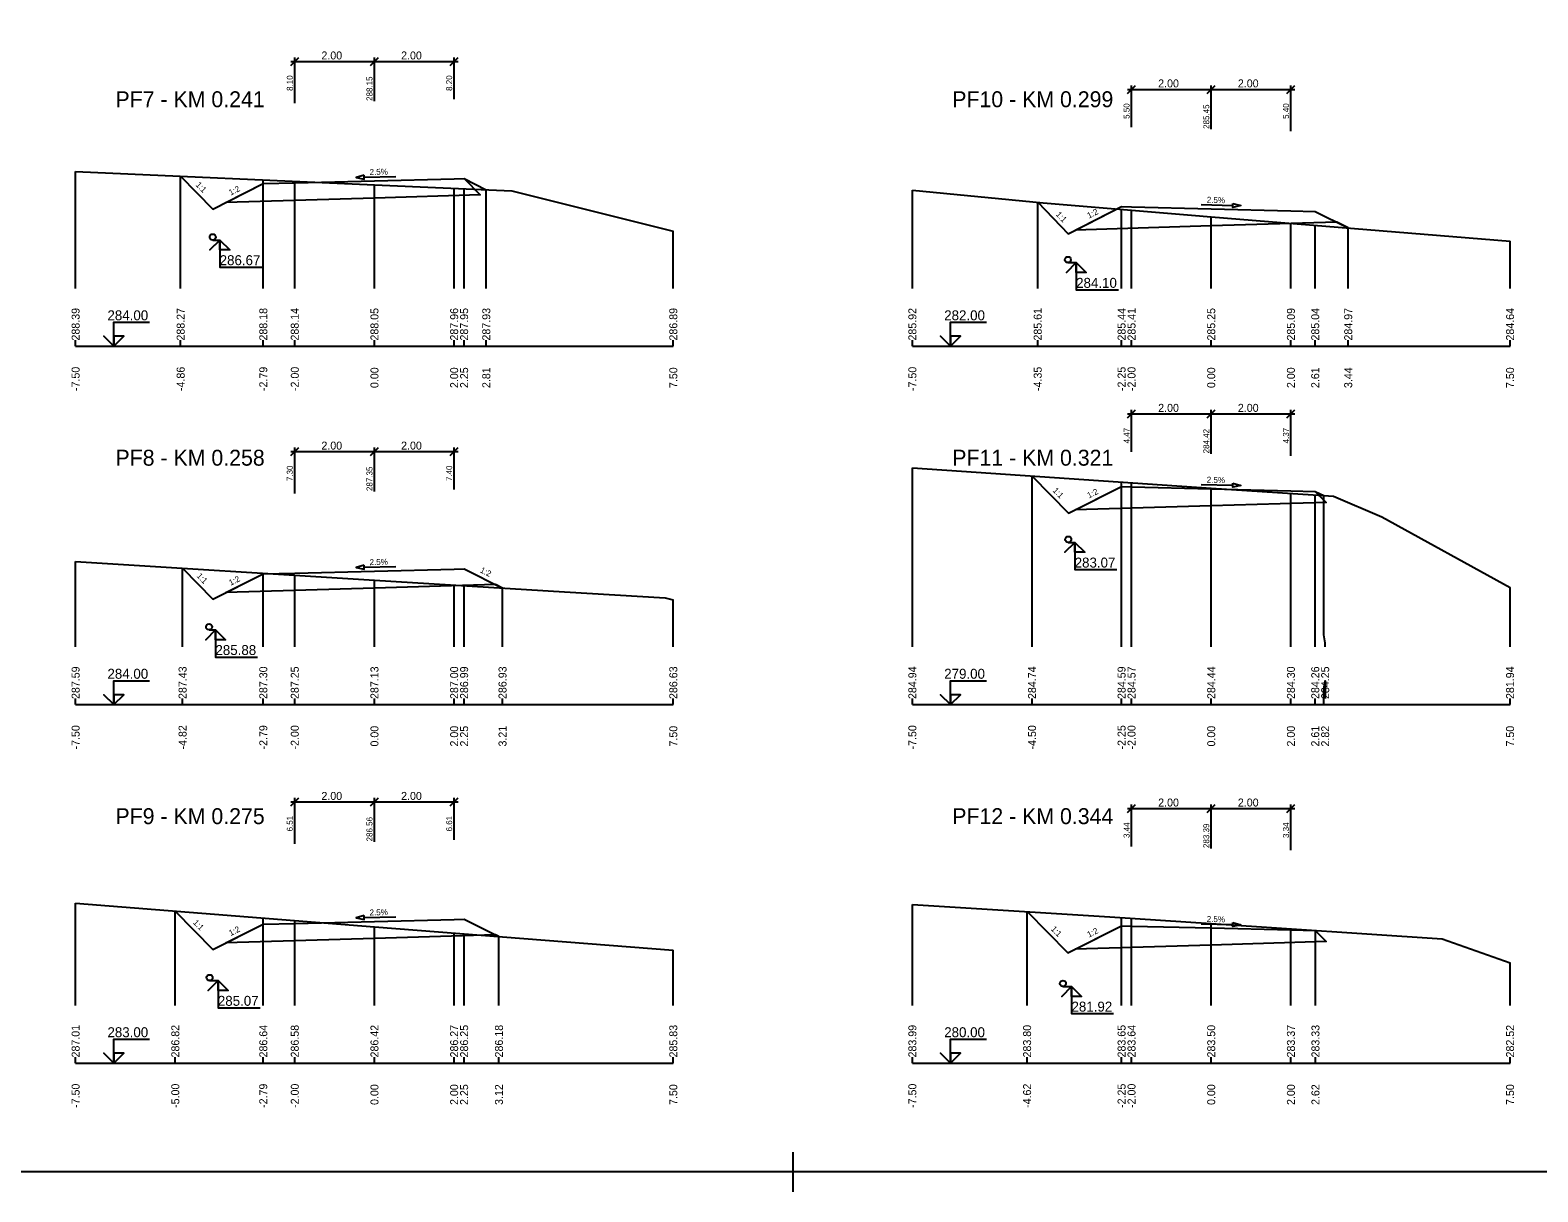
# Model space of a CAD drawing. Extents: x -5 to 1895, y -2 to 602.
# Drawn here: x 438.6 to 817, y -2.3 to 289.4 of the extents above; entities that cross this region are included whole.
import ezdxf

# ---------------------------------------------------------------- set-up
doc = ezdxf.new("R2010")
doc.units = 0
for name, color, linetype in [('KOTA', 7, 'Continuous'), ('KOTA_DELKY', 7, 'Continuous'), ('KOTA_DELKY_CONT', 7, 'Continuous'), ('KRIZENI', 7, 'Continuous'), ('NS_TELESO_VOZOVKY', 7, 'Continuous'), ('NS_V_PF', 7, 'Continuous'), ('REZY_PF_PUVODNI', 7, 'Continuous'), ('SESTAVY_REZU_PF', 7, 'Continuous'), ('SKLON', 7, 'Continuous'), ('SVK', 7, 'Continuous')]:
    doc.layers.add(name, color=color, linetype=linetype)

msp = doc.modelspace()

# ---------------------------------------------------------------- linework, layer by layer
for p, q in [((630, 7.67), (630, -2.33)), ((630, 7.67), (630, -2.33)), ((630, 7.67), (630, -2.33)), ((630, 7.67), (630, -2.33)), ((630, 7.67), (630, -2.33)), ((630, 7.67), (630, -2.33)), ((630, 7.67), (630, -2.33)), ((630, 7.67), (630, -2.33)), ((630, 7.67), (630, -2.33)), ((630, 7.67), (630, -2.33)), ((630, 7.67), (630, -2.33)), ((630, 7.67), (630, -2.33)), ((635, 2.67), (625, 2.67)), ((635, 2.67), (625, 2.67)), ((635, 2.67), (625, 2.67)), ((635, 2.67), (625, 2.67)), ((635, 2.67), (625, 2.67)), ((635, 2.67), (625, 2.67)), ((635, 2.67), (625, 2.67)), ((635, 2.67), (625, 2.67)), ((635, 2.67), (625, 2.67)), ((635, 2.67), (625, 2.67)), ((635, 2.67), (625, 2.67)), ((635, 2.67), (625, 2.67))]:
    msp.add_line(p, q)
msp.add_lwpolyline([(0, 596.67), (1890, 596.67), (1890, 2.67), (0, 2.67)], close=True)
at = {"layer": 'KOTA'}
for points in [[(486.2, 236.66), (483.7, 234.16), (486.2, 236.66), (486.2, 229.84), (496.74, 229.84)], [(484.41, 236.66), (486.2, 236.66)], [(486.2, 236.66), (488.7, 234.16), (486.2, 234.16), (486.2, 236.66)], [(486.2, 236.66), (488.7, 234.16), (486.2, 234.16)], [(701.14, 230.97), (698.64, 228.47), (701.14, 230.97), (701.14, 224.15), (711.69, 224.15)], [(699.03, 230.97), (701.14, 230.97)], [(701.14, 230.97), (703.64, 228.47), (701.14, 228.47), (701.14, 230.97)], [(701.14, 230.97), (703.64, 228.47), (701.14, 228.47)], [(459.57, 210), (457.07, 212.5), (459.57, 210), (459.57, 216), (468.57, 216)], [(669.57, 210), (667.07, 212.5), (669.57, 210), (669.57, 216), (678.57, 216)], [(459.57, 210), (462.07, 212.5), (459.57, 212.5), (459.57, 210)], [(459.57, 210), (462.07, 212.5), (459.57, 212.5)], [(669.57, 210), (672.07, 212.5), (669.57, 212.5), (669.57, 210)], [(669.57, 210), (672.07, 212.5), (669.57, 212.5)], [(700.78, 160.74), (698.28, 158.24), (700.78, 160.74), (700.78, 153.92), (711.32, 153.92)], [(699.13, 160.74), (700.78, 160.74)], [(700.78, 160.74), (703.28, 158.24), (700.78, 158.24), (700.78, 160.74)], [(700.78, 160.74), (703.28, 158.24), (700.78, 158.24)], [(485.14, 138.78), (482.64, 136.28), (485.14, 138.78), (485.14, 131.96), (495.68, 131.96)], [(483.49, 138.78), (485.14, 138.78)], [(485.14, 138.78), (487.64, 136.28), (485.14, 136.28), (485.14, 138.78)], [(485.14, 138.78), (487.64, 136.28), (485.14, 136.28)], [(459.57, 120), (457.07, 122.5), (459.57, 120), (459.57, 126), (468.57, 126)], [(669.57, 120), (667.07, 122.5), (669.57, 120), (669.57, 126), (678.57, 126)], [(459.57, 120), (462.07, 122.5), (459.57, 122.5), (459.57, 120)], [(459.57, 120), (462.07, 122.5), (459.57, 122.5)], [(669.57, 120), (672.07, 122.5), (669.57, 122.5), (669.57, 120)], [(669.57, 120), (672.07, 122.5), (669.57, 122.5)], [(485.75, 50.7), (483.25, 48.2), (485.75, 50.7), (485.75, 43.88), (496.29, 43.88)], [(483.63, 50.7), (485.75, 50.7)], [(485.75, 50.7), (488.25, 48.2), (485.75, 48.2), (485.75, 50.7)], [(485.75, 50.7), (488.25, 48.2), (485.75, 48.2)], [(699.97, 49.25), (697.47, 46.75), (699.97, 49.25), (699.97, 42.43), (710.51, 42.43)], [(697.79, 49.25), (699.97, 49.25)], [(699.97, 49.25), (702.47, 46.75), (699.97, 46.75), (699.97, 49.25)], [(699.97, 49.25), (702.47, 46.75), (699.97, 46.75)], [(459.57, 30), (457.07, 32.5), (459.57, 30), (459.57, 36), (468.57, 36)], [(669.57, 30), (667.07, 32.5), (669.57, 30), (669.57, 36), (678.57, 36)], [(459.57, 30), (462.07, 32.5), (459.57, 32.5), (459.57, 30)], [(459.57, 30), (462.07, 32.5), (459.57, 32.5)], [(669.57, 30), (672.07, 32.5), (669.57, 32.5), (669.57, 30)], [(669.57, 30), (672.07, 32.5), (669.57, 32.5)]]:
    msp.add_lwpolyline(points, dxfattribs=at)
at = {"layer": 'KOTA_DELKY'}
for points in [[(504, 280.5), (506, 282.5)], [(504, 281.5), (526, 281.5)], [(505, 271), (505, 282.5)], [(524, 280.5), (526, 282.5)], [(524, 280.5), (526, 282.5)], [(524, 281.5), (546, 281.5)], [(525, 271.5), (525, 282.5)], [(525, 271.5), (525, 282.5)], [(544, 280.5), (546, 282.5)], [(545, 272), (545, 282.5)], [(714, 273.48), (716, 275.48)], [(714, 274.48), (736, 274.48)], [(715, 264.98), (715, 275.48)], [(734, 273.48), (736, 275.48)], [(734, 273.48), (736, 275.48)], [(734, 274.48), (756, 274.48)], [(735, 264.48), (735, 275.48)], [(735, 264.48), (735, 275.48)], [(754, 273.48), (756, 275.48)], [(755, 263.98), (755, 275.48)], [(714, 192.01), (716, 194.01)], [(714, 193.01), (736, 193.01)], [(715, 183.51), (715, 194.01)], [(734, 192.01), (736, 194.01)], [(734, 192.01), (736, 194.01)], [(734, 193.01), (756, 193.01)], [(735, 183.01), (735, 194.01)], [(735, 183.01), (735, 194.01)], [(754, 192.01), (756, 194.01)], [(755, 182.51), (755, 194.01)], [(504, 182.54), (506, 184.54)], [(504, 183.54), (526, 183.54)], [(505, 173.04), (505, 184.54)], [(524, 182.54), (526, 184.54)], [(524, 182.54), (526, 184.54)], [(524, 183.54), (546, 183.54)], [(525, 173.54), (525, 184.54)], [(525, 173.54), (525, 184.54)], [(544, 182.54), (546, 184.54)], [(545, 174.04), (545, 184.54)], [(504, 94.58), (506, 96.58)], [(504, 95.58), (526, 95.58)], [(505, 85.08), (505, 96.58)], [(524, 94.58), (526, 96.58)], [(524, 94.58), (526, 96.58)], [(524, 95.58), (546, 95.58)], [(525, 85.58), (525, 96.58)], [(525, 85.58), (525, 96.58)], [(544, 94.58), (546, 96.58)], [(545, 86.08), (545, 96.58)], [(714, 92.92), (716, 94.92)], [(715, 84.42), (715, 94.92)], [(734, 92.92), (736, 94.92)], [(734, 92.92), (736, 94.92)], [(735, 83.92), (735, 94.92)], [(735, 83.92), (735, 94.92)], [(754, 92.92), (756, 94.92)], [(755, 83.42), (755, 94.92)], [(714, 93.92), (736, 93.92)], [(734, 93.92), (756, 93.92)]]:
    msp.add_lwpolyline(points, dxfattribs=at)
at = {"layer": 'KRIZENI'}
for centre in [(484.41, 237.41), (699.03, 231.72), (699.13, 161.49), (483.49, 139.53), (483.63, 51.45), (697.79, 50)]:
    msp.add_circle(centre, 0.75, dxfattribs=at)
at = {"layer": 'NS_TELESO_VOZOVKY'}
for points in [[(525, 251.5), (545, 252), (547.5, 252.07), (551.57, 248), (525, 247.2), (487.74, 246.09), (497.1, 250.81), (505, 251), (525, 251.5)], [(735, 244.48), (755, 243.98), (761.1, 243.83), (769.38, 239.69), (766.5, 241.13), (735, 240.18), (700.92, 239.16), (712.5, 245.04), (715, 244.98), (735, 244.48)], [(735, 174.2), (755, 173.7), (761.1, 173.55), (763.88, 170.77), (735, 169.9), (700.86, 168.88), (712.5, 174.77), (715, 174.7), (735, 174.2)], [(525, 153.54), (545, 154.04), (547.5, 154.1), (557.14, 149.28), (555.4, 150.15), (525, 149.24), (487.74, 148.12), (497.1, 152.84), (505, 153.04), (525, 153.54)], [(525, 65.58), (545, 66.08), (547.5, 66.14), (556.24, 61.77), (555.4, 62.19), (525, 61.28), (487.74, 60.16), (497.1, 64.88), (505, 65.08), (525, 65.58)], [(735, 63.92), (755, 63.42), (761.1, 63.27), (763.88, 60.49), (735, 59.62), (700.86, 58.6), (712.5, 64.49), (715, 64.42), (735, 63.92)]]:
    msp.add_lwpolyline(points, dxfattribs=at)
at = {"layer": 'NS_V_PF'}
for points in [[(476.36, 252.71), (484.47, 244.43), (497.1, 250.81), (505, 251), (525, 251.5), (545, 252), (547.5, 252.07), (553.06, 249.29)], [(691.45, 246.12), (699.08, 238.22), (712.5, 245.04), (715, 244.98), (735, 244.48), (755, 243.98), (761.1, 243.83), (769.38, 239.69)], [(690.04, 177.4), (699.19, 168.04), (712.5, 174.77), (715, 174.7), (735, 174.2), (755, 173.7), (761.1, 173.55), (763.24, 172.48)], [(476.84, 154.25), (484.47, 146.47), (497.1, 152.84), (505, 153.04), (525, 153.54), (545, 154.04), (547.5, 154.1), (557.14, 149.28)], [(475.02, 68.15), (484.47, 58.51), (497.1, 64.88), (505, 65.08), (525, 65.58), (545, 66.08), (547.5, 66.14), (556.24, 61.77)], [(688.82, 68.05), (699.01, 57.66), (712.5, 64.49), (715, 64.42), (735, 63.92), (755, 63.42), (761.1, 63.27), (761.16, 63.3)]]:
    msp.add_lwpolyline(points, dxfattribs=at)
at = {"layer": 'REZY_PF_PUVODNI'}
for points in [[(450, 253.88), (525, 250.54), (559.5, 249), (600, 238.86)], [(660, 249.17), (692.85, 245.98), (730.08, 242.9), (735, 242.5), (735, 242.5), (810, 236.37)], [(660, 179.42), (735, 174.38), (735, 174.38), (765.65, 172.32), (777.79, 167.19), (810, 149.43)], [(450, 155.91), (525, 151.27), (572.73, 148.32), (597.96, 146.85), (600, 146.33)], [(450, 70.12), (525, 64.23), (525, 64.23), (600, 58.34)], [(660, 69.86), (709.57, 66.74), (735, 65.05), (792.95, 61.19), (810, 55.18)]]:
    msp.add_lwpolyline(points, dxfattribs=at)
at = {"layer": 'SESTAVY_REZU_PF'}
for points in [[(450, 210), (600, 210)], [(660, 210), (810, 210)], [(450, 120), (600, 120)], [(660, 120), (810, 120)], [(450, 30), (600, 30)], [(660, 30), (810, 30)]]:
    msp.add_lwpolyline(points, dxfattribs=at)
at = {"layer": 'SKLON'}
for points in [[(522.39, 252.94), (520.4, 252.39), (522.41, 251.94), (522.39, 252.94)], [(522.4, 252.44), (530.4, 252.64)], [(732.45, 245.55), (740.45, 245.35)], [(740.46, 245.85), (742.45, 245.3), (740.43, 244.85), (740.46, 245.85)], [(732.45, 175.27), (740.45, 175.07)], [(740.46, 175.57), (742.45, 175.02), (740.43, 174.57), (740.46, 175.57)], [(522.39, 154.98), (520.4, 154.43), (522.41, 153.98), (522.39, 154.98)], [(522.4, 154.48), (530.4, 154.68)], [(522.39, 67.02), (520.4, 66.47), (522.41, 66.02), (522.39, 67.02)], [(522.4, 66.52), (530.4, 66.72)], [(732.45, 64.99), (740.45, 64.79)], [(740.46, 65.29), (742.45, 64.74), (740.43, 64.29), (740.46, 65.29)]]:
    msp.add_lwpolyline(points, dxfattribs=at)
for points in [[(522.39, 252.94), (520.4, 252.39), (522.41, 251.94)], [(740.46, 245.85), (742.45, 245.3), (740.43, 244.85)], [(740.46, 175.57), (742.45, 175.02), (740.43, 174.57)], [(522.39, 154.98), (520.4, 154.43), (522.41, 153.98)], [(522.39, 67.02), (520.4, 66.47), (522.41, 66.02)], [(740.46, 65.29), (742.45, 64.74), (740.43, 64.29)]]:
    msp.add_lwpolyline(points, close=True, dxfattribs=at)
at = {"layer": 'SVK'}
for points in [[(450, 224.5), (450, 253.88)], [(476.36, 224.5), (476.36, 252.71)], [(497.1, 224.5), (497.1, 251.78)], [(505, 224.5), (505, 251.43)], [(525, 224.5), (525, 250.54)], [(545, 224.5), (545, 249.65)], [(547.5, 224.5), (547.5, 249.54)], [(553.06, 224.5), (553.06, 249.29)], [(660, 224.5), (660, 249.17)], [(691.45, 224.5), (691.45, 246.12)], [(712.5, 224.5), (712.5, 244.36)], [(715, 224.5), (715, 244.15)], [(735, 224.5), (735, 242.5)], [(600, 224.5), (600, 238.86)], [(755, 224.5), (755, 240.86)], [(761.1, 224.5), (761.1, 240.37)], [(769.38, 224.5), (769.38, 239.69)], [(810, 224.5), (810, 236.37)], [(450, 210), (450, 211.5)], [(476.36, 210), (476.36, 211.5)], [(497.1, 210), (497.1, 211.5)], [(505, 210), (505, 211.5)], [(525, 210), (525, 211.5)], [(545, 210), (545, 211.5)], [(547.5, 210), (547.5, 211.5)], [(553.06, 210), (553.06, 211.5)], [(600, 210), (600, 211.5)], [(660, 210), (660, 211.5)], [(691.45, 210), (691.45, 211.5)], [(712.5, 210), (712.5, 211.5)], [(715, 210), (715, 211.5)], [(735, 210), (735, 211.5)], [(755, 210), (755, 211.5)], [(761.1, 210), (761.1, 211.5)], [(769.38, 210), (769.38, 211.5)], [(810, 210), (810, 211.5)], [(660, 134.5), (660, 179.42)], [(690.03, 134.5), (690.03, 177.4)], [(712.5, 134.5), (712.5, 175.89)], [(715, 134.5), (715, 175.72)], [(735, 134.5), (735, 174.38)], [(755, 134.5), (755, 173.03)], [(761.1, 134.5), (761.1, 172.62)], [(763.6, 134.5), (763.6, 135.5), (763.24, 137.5), (763.24, 172.48)], [(450, 134.5), (450, 155.91)], [(476.84, 134.5), (476.84, 154.25)], [(497.1, 134.5), (497.1, 153)], [(505, 134.5), (505, 152.51)], [(525, 134.5), (525, 151.27)], [(545, 134.5), (545, 150.03)], [(547.5, 134.5), (547.5, 149.88)], [(557.14, 134.5), (557.14, 149.28)], [(810, 134.5), (810, 149.43)], [(600, 134.5), (600, 146.33)], [(763.24, 120), (763.24, 124), (763.6, 126), (763.6, 121.5)], [(450, 120), (450, 121.5)], [(476.84, 120), (476.84, 121.5)], [(497.1, 120), (497.1, 121.5)], [(505, 120), (505, 121.5)], [(525, 120), (525, 121.5)], [(545, 120), (545, 121.5)], [(547.5, 120), (547.5, 121.5)], [(557.14, 120), (557.14, 121.5)], [(600, 120), (600, 121.5)], [(660, 120), (660, 121.5)], [(690.03, 120), (690.03, 121.5)], [(712.5, 120), (712.5, 121.5)], [(715, 120), (715, 121.5)], [(735, 120), (735, 121.5)], [(755, 120), (755, 121.5)], [(761.1, 120), (761.1, 121.5)], [(810, 120), (810, 121.5)], [(450, 44.5), (450, 70.12)], [(475.02, 44.5), (475.02, 68.15)], [(660, 44.5), (660, 69.86)], [(497.1, 44.5), (497.1, 66.42)], [(505, 44.5), (505, 65.8)], [(688.79, 44.5), (688.79, 68.05)], [(712.5, 44.5), (712.5, 66.54)], [(715, 44.5), (715, 66.38)], [(735, 44.5), (735, 65.05)], [(525, 44.5), (525, 64.23)], [(545, 44.5), (545, 62.66)], [(547.5, 44.5), (547.5, 62.46)], [(556.24, 44.5), (556.24, 61.77)], [(755, 44.5), (755, 63.71)], [(761.16, 44.5), (761.16, 63.3)], [(600, 44.5), (600, 58.34)], [(810, 44.5), (810, 55.18)], [(450, 30), (450, 31.5)], [(475.02, 30), (475.02, 31.5)], [(497.1, 30), (497.1, 31.5)], [(505, 30), (505, 31.5)], [(525, 30), (525, 31.5)], [(545, 30), (545, 31.5)], [(547.5, 30), (547.5, 31.5)], [(556.24, 30), (556.24, 31.5)], [(600, 30), (600, 31.5)], [(660, 30), (660, 31.5)], [(688.79, 30), (688.79, 31.5)], [(712.5, 30), (712.5, 31.5)], [(715, 30), (715, 31.5)], [(735, 30), (735, 31.5)], [(755, 30), (755, 31.5)], [(761.16, 30), (761.16, 31.5)], [(810, 30), (810, 31.5)]]:
    msp.add_lwpolyline(points, dxfattribs=at)

# ---------------------------------------------------------------- texts
at = {"layer": 'KOTA'}
for s, p in [('286.67', (486.15, 230.34)), ('284.10', (701.1, 224.65)), ('284.00', (457.99, 216.5)), ('282.00', (667.99, 216.5)), ('283.07', (700.73, 154.42)), ('285.88', (485.09, 132.46)), ('284.00', (457.99, 126.5)), ('279.00', (667.99, 126.5)), ('285.07', (485.7, 44.38)), ('281.92', (699.93, 42.93)), ('283.00', (457.99, 36.5)), ('280.00', (667.99, 36.5))]:
    msp.add_text(s, height=2.5, dxfattribs=at).set_placement(p)
at = {"layer": 'KOTA_DELKY'}
for p in [(511.69, 282), (531.69, 282), (721.69, 274.98), (741.69, 274.98), (721.69, 193.51), (741.69, 193.51), (511.69, 184.04), (531.69, 184.04), (511.69, 96.08), (531.69, 96.08), (721.69, 94.42), (741.69, 94.42)]:
    msp.add_text('2.00', height=2, dxfattribs=at).set_placement(p)
at = {"layer": 'KOTA_DELKY_CONT'}
for s, p in [('8.10', (504.5, 274.09)), ('288.15', (524.5, 271.58)), ('8.20', (544.5, 274.09)), ('5.50', (714.5, 267.07)), ('285.45', (734.5, 264.56)), ('5.40', (754.5, 267.07)), ('4.47', (714.5, 185.6)), ('4.37', (754.5, 185.6)), ('284.42', (734.5, 183.09)), ('7.30', (504.5, 176.13)), ('287.35', (524.5, 173.62)), ('7.40', (544.5, 176.13)), ('6.51', (504.5, 88.17)), ('286.56', (524.5, 85.66)), ('6.61', (544.5, 88.17)), ('3.44', (714.5, 86.51)), ('283.39', (734.5, 84)), ('3.34', (754.5, 86.51))]:
    msp.add_text(s, height=1.5, rotation=90, dxfattribs=at).set_placement(p)
at = {"layer": 'SESTAVY_REZU_PF'}
for s, p in [('PF7 - KM 0.241', (460, 270)), ('PF10 - KM 0.299', (670, 270)), ('PF8 - KM 0.258', (460, 180)), ('PF11 - KM 0.321', (670, 180)), ('PF9 - KM 0.275', (460, 90)), ('PF12 - KM 0.344', (670, 90))]:
    msp.add_text(s, height=4, dxfattribs=at).set_placement(p)
at = {"layer": 'SKLON'}
for s, rotation, p in [('2.5%', 1.4321, (523.8, 252.97)), ('1:1', 314.4213, (480.02, 250.4)), ('1:2', 26.7649, (488.92, 247.8)), ('2.5%', 358.5679, (733.87, 246.01)), ('1:1', 313.9941, (695.9, 242.95)), ('1:2', 26.9444, (704.32, 242.01)), ('1:1', 314.326, (695.1, 173.65)), ('1:2', 26.8191, (704.32, 171.75)), ('2.5%', 358.5679, (733.87, 175.73)), ('2.5%', 1.4321, (523.8, 155.01)), ('1:1', 314.4213, (480.26, 152.19)), ('1:2', 26.7649, (488.92, 149.84)), ('1:2', 333.4349, (551.36, 153.29)), ('2.5%', 1.4321, (523.8, 67.05)), ('1:1', 314.4213, (479.35, 65.16)), ('1:2', 26.7649, (488.92, 61.88)), ('2.5%', 358.5679, (733.87, 65.45)), ('1:1', 314.4526, (694.65, 63.54)), ('1:2', 26.8284, (704.32, 61.47))]:
    msp.add_text(s, height=1.5, rotation=rotation, dxfattribs=at).set_placement(p)
at = {"layer": 'SVK'}
for s, p in [(' 288.39', (451, 210.67)), (' 288.18', (498.1, 210.67)), (' 288.14', (506, 210.67)), (' 288.05', (526, 210.67)), (' 287.96', (546, 210.67)), (' 287.95', (548.5, 210.67)), (' 287.93', (554.06, 210.67)), (' 286.89', (601, 210.67)), (' 285.61', (692.45, 210.67)), (' 285.44', (713.5, 210.67)), (' 285.41', (716, 210.67)), (' 285.25', (736, 210.67)), (' 285.09', (756, 210.67)), (' 285.04', (762.1, 210.67)), (' 284.64', (811, 210.67)), (' 288.27', (477.36, 210.67)), (' 285.92', (661, 210.67)), (' 284.97', (770.38, 210.67)), (' -7.50', (451, 198)), (' -4.86', (477.36, 198)), (' -2.79', (498.1, 198)), (' -2.00', (506, 198)), ('  0.00', (526, 198)), ('  2.00', (546, 198)), ('  2.25', (548.5, 198)), ('  2.81', (554.06, 198)), ('  7.50', (601, 198)), (' -7.50', (661, 198)), (' -4.35', (692.45, 198)), (' -2.25', (713.5, 198)), (' -2.00', (716, 198)), ('  0.00', (736, 198)), ('  2.00', (756, 198)), ('  2.61', (762.1, 198)), ('  3.44', (770.38, 198)), ('  7.50', (811, 198)), (' 287.59', (451, 120.67)), (' 287.43', (477.84, 120.67)), (' 287.30', (498.1, 120.67)), (' 287.25', (506, 120.67)), (' 287.13', (526, 120.67)), (' 287.00', (546, 120.67)), (' 286.99', (548.5, 120.67)), (' 286.93', (558.14, 120.67)), (' 286.63', (601, 120.67)), (' 284.94', (661, 120.67)), (' 284.74', (691.03, 120.67)), (' 284.59', (713.5, 120.67)), (' 284.57', (716, 120.67)), (' 284.44', (736, 120.67)), (' 284.30', (756, 120.67)), (' 284.26', (762.1, 120.67)), (' 284.25', (764.6, 120.67)), (' 281.94', (811, 120.67)), (' -7.50', (451, 108)), (' -4.82', (477.84, 108)), (' -2.79', (498.1, 108)), (' -2.00', (506, 108)), ('  0.00', (526, 108)), ('  2.00', (546, 108)), ('  2.25', (548.5, 108)), ('  3.21', (558.14, 108)), ('  7.50', (601, 108)), (' -7.50', (661, 108)), (' -4.50', (691.03, 108)), (' -2.25', (713.5, 108)), (' -2.00', (716, 108)), ('  0.00', (736, 108)), ('  2.00', (756, 108)), ('  2.61', (762.1, 108)), ('  2.82', (764.6, 108)), ('  7.50', (811, 108)), (' 287.01', (451, 30.67)), (' 286.82', (476.02, 30.67)), (' 286.64', (498.1, 30.67)), (' 286.58', (506, 30.67)), (' 286.42', (526, 30.67)), (' 286.27', (546, 30.67)), (' 286.25', (548.5, 30.67)), (' 286.18', (557.24, 30.67)), (' 285.83', (601, 30.67)), (' 283.99', (661, 30.67)), (' 283.80', (689.79, 30.67)), (' 283.65', (713.5, 30.67)), (' 283.64', (716, 30.67)), (' 283.50', (736, 30.67)), (' 283.37', (756, 30.67)), (' 283.33', (762.16, 30.67)), (' 282.52', (811, 30.67)), (' -7.50', (451, 18)), (' -5.00', (476.02, 18)), (' -2.79', (498.1, 18)), (' -2.00', (506, 18)), ('  0.00', (526, 18)), ('  2.00', (546, 18)), ('  2.25', (548.5, 18)), ('  3.12', (557.24, 18)), ('  7.50', (601, 18)), (' -7.50', (661, 18)), (' -4.62', (689.79, 18)), (' -2.25', (713.5, 18)), (' -2.00', (716, 18)), ('  0.00', (736, 18)), ('  2.00', (756, 18)), ('  2.62', (762.16, 18)), ('  7.50', (811, 18))]:
    msp.add_text(s, height=2, rotation=90, dxfattribs=at).set_placement(p)

doc.saveas('drawing.dxf')
